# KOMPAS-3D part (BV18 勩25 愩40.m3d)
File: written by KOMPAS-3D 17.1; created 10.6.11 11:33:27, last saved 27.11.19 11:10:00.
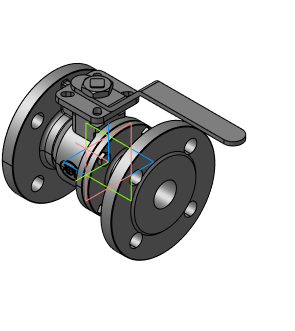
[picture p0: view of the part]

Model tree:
1. Плоскость XY
2. Плоскость ZX
3. Плоскость ZY
4. Ось X
5. Ось Y
6. Ось Z
7. Начало координат
8. Операция без истории:5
